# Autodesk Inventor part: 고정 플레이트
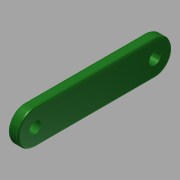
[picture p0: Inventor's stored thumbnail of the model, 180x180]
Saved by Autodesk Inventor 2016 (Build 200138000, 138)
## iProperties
Created: 2017-04
Part Number: 고정 플레이트
Material: 스테인리스강
Document SubType Name: Modeling
Designer: mduedu
Density: 8.08 g/cm^3
Appearance: 매끄러움 - 짙은 산림 녹색
Mass: 9.86033 g
Surface Area: 11.4535 cm^2
Volume: 1.22034 cm^3
Author: mduedu
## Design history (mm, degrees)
sketch "스케치1"
  geometry: L1 (0, 17.5)-(0, -17.5); L2 (-5, 17.5)-(-5, -17.5); L3 (5, -17.5)-(5, 17.5); A1 r 5 centre (0, 17.5) between (5, 17.5) and (-5, 17.5); A2 r 5 centre (0, -17.5) between (-5, -17.5) and (5, -17.5); 2 further points
  constraints: 6 end point, 4 point on circle, 4 tangent, 3 coincident, 2 centre point, 1 midpoint, 1 parallel, 1 vertical
  dimensions: "d0" = 35 distance of L1.start L1.end; "d1" = 5 radius of A2
extrude "돌출1" new body sketch "스케치1" distance "d2" = 3; taper "d3" = 0 deg
fillet "모깎기1" dims "d4" = 0.5
sketch "스케치2"
  geometry: A1 r 5 centre (-17.5, 0) between (-17.5, 5) and (-17.5, -5) reference; A2 r 5 centre (17.5, 0) between (17.5, -5) and (17.5, 5) reference; 3 further points
  constraints: 2 coincident
sketch "스케치3"
  geometry: 3 further points
  constraints: 3 other
hole "구멍1" sketch "스케치3" at (-17.5, 0), (17.5, 0) diameter "d5" = 3.4; stored, may be unused: countersink angle "d9" = 90 deg, drill point angle "d11" = 0 deg; dims "d6" = 6, "d7" = 4, "d8" = 2, "d10" = 8
node "솔리드1"
